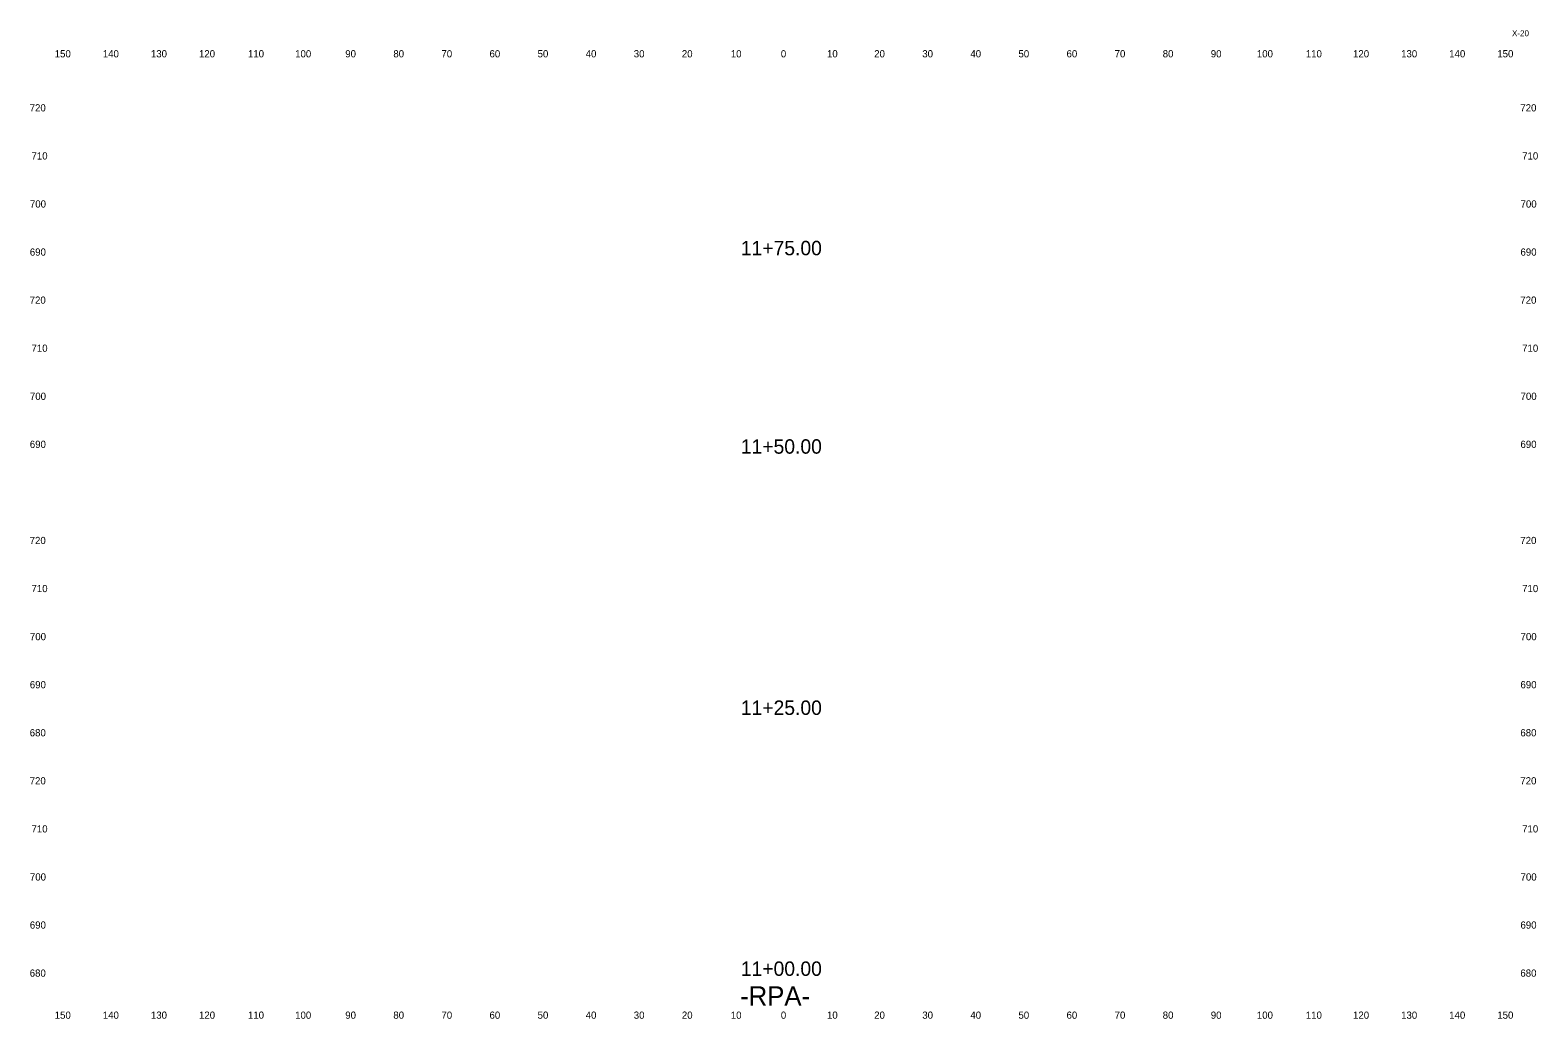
# Model space of a CAD drawing. Extents: x 3 to 317, y 1 to 867.
# Drawn here: x 3.3 to 316.9, y 221.2 to 426.9 of the extents above; entities that cross this region are included whole.
import ezdxf

# ---------------------------------------------------------------- set-up
doc = ezdxf.new("R2010")
doc.units = 0
for name, color, linetype in [('Prop XS Alignment Label', 7, 'Continuous'), ('Prop XS Elevation Labels', 7, 'Continuous'), ('Prop XS Offset Labels', 7, 'Continuous'), ('Prop XS Sheet Number', 7, 'Continuous'), ('Prop XS Station Labels', 7, 'Continuous')]:
    doc.layers.add(name, color=color, linetype=linetype)

msp = doc.modelspace()

# ---------------------------------------------------------------- texts
at = {"layer": 'Prop XS Alignment Label'}
msp.add_text('-RPA-', height=4, dxfattribs=at).set_placement((150.97, 224))
at = {"layer": 'Prop XS Elevation Labels'}
for s, p in [('720', (3.23, 410)), ('720', (313.23, 410)), ('710', (3.61, 400)), ('710', (313.61, 400)), ('700', (3.28, 390)), ('700', (313.28, 390)), ('690', (3.26, 380)), ('690', (313.26, 380)), ('720', (3.23, 370)), ('720', (313.23, 370)), ('710', (3.61, 360)), ('710', (313.61, 360)), ('700', (3.28, 350)), ('700', (313.28, 350)), ('690', (3.26, 340)), ('690', (313.26, 340)), ('720', (3.23, 320)), ('720', (313.23, 320)), ('710', (3.61, 310)), ('710', (313.61, 310)), ('700', (3.28, 300)), ('700', (313.28, 300)), ('690', (3.26, 290)), ('690', (313.26, 290)), ('680', (3.24, 280)), ('680', (313.24, 280)), ('720', (3.23, 270)), ('720', (313.23, 270)), ('710', (3.61, 260)), ('710', (313.61, 260)), ('700', (3.28, 250)), ('700', (313.28, 250)), ('690', (3.26, 240)), ('690', (313.26, 240)), ('680', (3.24, 230)), ('680', (313.24, 230))]:
    msp.add_text(s, height=1.5, dxfattribs=at).set_placement(p)
at = {"layer": 'Prop XS Offset Labels'}
for s, p in [('150', (8.44, 421.25)), ('140', (18.44, 421.25)), ('130', (28.44, 421.25)), ('120', (38.44, 421.25)), ('110', (48.62, 421.25)), ('100', (58.44, 421.25)), ('90', (68.86, 421.25)), ('80', (78.86, 421.25)), ('70', (88.86, 421.25)), ('60', (98.86, 421.25)), ('50', (108.86, 421.25)), ('40', (118.86, 421.25)), ('30', (128.86, 421.25)), ('20', (138.86, 421.25)), ('10', (149.04, 421.25)), ('0', (159.45, 421.25)), ('10', (169.04, 421.25)), ('20', (178.86, 421.25)), ('30', (188.86, 421.25)), ('40', (198.86, 421.25)), ('50', (208.86, 421.25)), ('60', (218.86, 421.25)), ('70', (228.86, 421.25)), ('80', (238.86, 421.25)), ('90', (248.86, 421.25)), ('100', (258.44, 421.25)), ('110', (268.62, 421.25)), ('120', (278.44, 421.25)), ('130', (288.44, 421.25)), ('140', (298.44, 421.25)), ('150', (308.44, 421.25)), ('150', (8.44, 221.25)), ('140', (18.44, 221.25)), ('130', (28.44, 221.25)), ('120', (38.44, 221.25)), ('110', (48.62, 221.25)), ('100', (58.44, 221.25)), ('90', (68.86, 221.25)), ('80', (78.86, 221.25)), ('70', (88.86, 221.25)), ('60', (98.86, 221.25)), ('50', (108.86, 221.25)), ('40', (118.86, 221.25)), ('30', (128.86, 221.25)), ('20', (138.86, 221.25)), ('10', (149.04, 221.25)), ('0', (159.45, 221.25)), ('10', (169.04, 221.25)), ('20', (178.86, 221.25)), ('30', (188.86, 221.25)), ('40', (198.86, 221.25)), ('50', (208.86, 221.25)), ('60', (218.86, 221.25)), ('70', (228.86, 221.25)), ('80', (238.86, 221.25)), ('90', (248.86, 221.25)), ('100', (258.44, 221.25)), ('110', (268.62, 221.25)), ('120', (278.44, 221.25)), ('130', (288.44, 221.25)), ('140', (298.44, 221.25)), ('150', (308.44, 221.25))]:
    msp.add_text(s, height=1.5, dxfattribs=at).set_placement(p)
at = {"layer": 'Prop XS Sheet Number'}
msp.add_text('X-20', height=1.25, dxfattribs=at).set_placement((311.5, 425.64))
at = {"layer": 'Prop XS Station Labels'}
for s, p in [('11+75.00', (151.13, 380.08)), ('11+50.00', (151.13, 338.8)), ('11+25.00', (151.13, 284.46)), ('11+00.00', (151.13, 230.17))]:
    msp.add_text(s, height=3, dxfattribs=at).set_placement(p)

doc.saveas('drawing.dxf')
